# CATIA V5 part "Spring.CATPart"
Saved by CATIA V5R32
Part number: Part1
Bounding box of the stored display mesh (mm): x -50 to 50, y -44.999 to 44.983, z -4.984 to 154.984
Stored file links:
  D:\PROJECTS\Project 2022\CATIA V5 6R 2022\Resources\Tutorial Files\c19_catia_v5_6r2022_tut\C19_tut_01.CATPart\Spring.CATPart
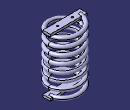
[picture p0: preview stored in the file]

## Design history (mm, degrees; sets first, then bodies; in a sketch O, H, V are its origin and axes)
Body1 (main body)
  Point1: (0, 0, 0)
  Point2: (0, 0, 150)
  Line1: type PtPt, FirstPoint Point2, SecondPoint Point1
  Point3: (40, 0, 0)
  Helix1: Direction Line1, RefPoint Point3, Pitch 20, Height 150, TaperAngle 0, Revolutions 1
  Plane1: type Normal, Curve Helix1, RefPoint vertex of Helix1, Ratio 0
  Sketch1 on Plane1, origin (0, -11.8615, 0.9439), H (1, 0, 0), V (0, 0.0793, 0.9968)
    circle A1 centre (-40, 149.5273) radius 5
    point P1 (-40, 149.5273)
    reference projected point E1 (-40, 149.5273) from vertex of Helix1
    radius A1 = 5
    coincidence: P1 E1
  Rib1: profile Sketch1, centre curve Helix1
  Sketch2 on xy-plane, origin (0, 0, 0), H (1, 0, 0), V (0, 1, 0)
    line L1 (-50, 10) -> (50, 10)
    line L2 (50, 10) -> (50, -10)
    line L3 (50, -10) -> (-50, -10)
    line L4 (-50, -10) -> (-50, 10)
    length L1 = 100
    distance L1 L3 = 20
    horizontal: L1 H, L3 H
    vertical: L2 V, L4 V
    symmetry: L3 L1 H, L2 L4 V
  Pad1: profile Sketch2, direction (0, 0, 1), length 3, mirrored extent
  Sketch3 on start face of Pad1, origin (0, 0, -3), H (1, 0, 0), V (0, -1, 0)
    circle A1 centre (-24.223, 0) radius 2.5
    point P1 (-24.223, 0)
    circle A2 centre (24.223, 0) radius 2.5
    point P2 (24.223, 0)
    radius A2 = 2.5
    coincidence: P1 H, P2 H
    symmetry: A2 A1 V
  Pocket1: profile Sketch3, direction (0, 0, 1), length 3
  Plane2: type Offset, RefPlane xy-plane, Offset 150
  Sketch4 on Plane2, origin (0, 0, 150), H (1, 0, 0), V (0, 1, 0)
    line L1 (-50, 10) -> (50, 10)
    line L2 (50, 10) -> (50, -10)
    line L3 (50, -10) -> (-50, -10)
    line L4 (-50, -10) -> (-50, 10)
    reference projected line E1 (50, -10) -> (50, 10) from edge [face of Pad1 from Sketch2.L2 | end face of Pad1]
    reference projected line E2 (-50, 10) -> (-50, -10) from edge [face of Pad1 from Sketch2.L4 | end face of Pad1]
    reference projected line E3 (-50, -10) -> (50, -10) from edge [face of Pad1 from Sketch2.L3 | end face of Pad1]
    reference projected line E4 (50, 10) -> (-50, 10) from edge [face of Pad1 from Sketch2.L1 | end face of Pad1]
    horizontal: L1 H, L3 H
    vertical: L2 V, L4 V
    coincidence: L2 E1, L4 E2, E3 L3, L1 E4
  Pad2: profile Sketch4, direction (0, 0, 1), length 3, mirrored extent
  Sketch5 on end face of Pad2, origin (0, 0, 153), H (1, 0, 0), V (0, 1, 0)
    circle A1 centre (-20.0406, 0) radius 2.5674
    point P1 (-20.0406, 0)
    circle A2 centre (20.0406, 0) radius 2.5674
    coincidence: P1 H
    symmetry: A1 A2 V
  Pocket2: profile Sketch5, direction (0, 0, -1), through (limit type 6)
